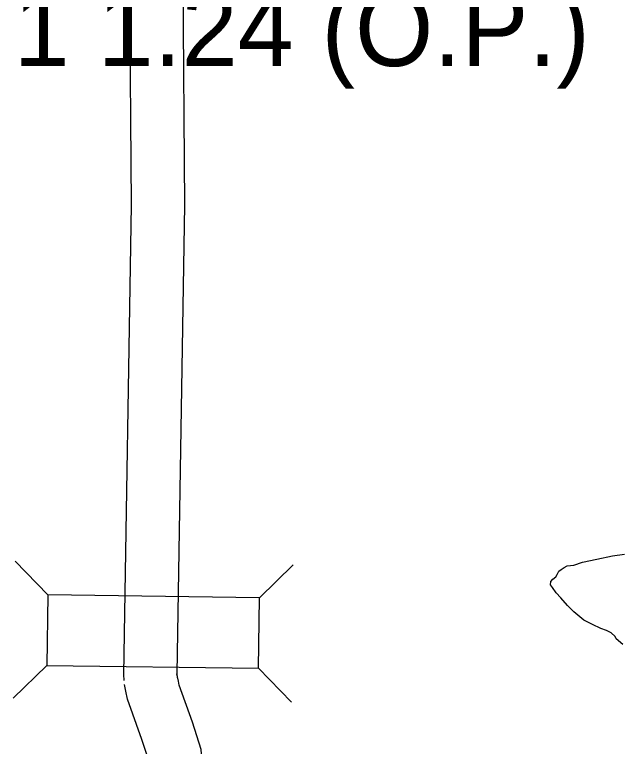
# Model space of a CAD drawing. Extents: x -939622 to -934245, y 1383184 to 1385301.
# Drawn here: x -936403.59 to -936393.44, y 1384587.4 to 1384599.72 of the extents above; entities that cross this region are included whole.
import ezdxf

# ---------------------------------------------------------------- set-up
doc = ezdxf.new("R2010")
doc.units = 0
for name, color, linetype in [('Level 10', 7, 'Continuous'), ('Level 20', 7, 'Continuous'), ('Level 25', 7, 'Continuous'), ('Level 9', 7, 'Continuous')]:
    doc.layers.add(name, color=color, linetype=linetype)

msp = doc.modelspace()

# ---------------------------------------------------------------- linework, layer by layer
at = {"layer": 'Level 10'}
for points in [[(-936400.851, 1384588.552), (-936400.855, 1384588.625), (-936400.726, 1384596.507), (-936400.757, 1384600.262)], [(-936401.75, 1384588.506), (-936401.756, 1384588.609), (-936401.626, 1384596.511), (-936401.656, 1384600.127)], [(-936397.363, 1384579.247), (-936400.098, 1384583.042), (-936400.103, 1384583.052), (-936400.111, 1384583.136), (-936400.436, 1384587.126), (-936400.45, 1384587.342), (-936400.526, 1384587.573), (-936400.601, 1384587.803), (-936400.823, 1384588.429), (-936400.835, 1384588.496), (-936400.86, 1384588.617)], [(-936398.093, 1384578.72), (-936400.861, 1384582.561), (-936400.934, 1384582.695), (-936400.989, 1384582.852), (-936401.008, 1384583.061), (-936401.334, 1384587.062), (-936401.341, 1384587.171), (-936401.381, 1384587.293), (-936401.453, 1384587.513), (-936401.694, 1384588.194), (-936401.719, 1384588.325), (-936401.742, 1384588.441)]]:
    msp.add_lwpolyline(points, dxfattribs=at)
at = {"layer": 'Level 20'}
for p, q in [((-936403.033, 1384589.949), (-936403.586, 1384590.517)), ((-936399.47, 1384589.9), (-936398.902, 1384590.452)), ((-936403.05, 1384588.761), (-936403.618, 1384588.209)), ((-936399.486, 1384588.712), (-936398.934, 1384588.144))]:
    msp.add_line(p, q, dxfattribs=at)
msp.add_lwpolyline([(-936403.05, 1384588.761), (-936399.486, 1384588.712), (-936399.47, 1384589.9), (-936403.033, 1384589.949)], close=True, dxfattribs=at)
at = {"layer": 'Level 9'}
msp.add_lwpolyline([(-936393.352, 1384589.111), (-936393.464, 1384589.206), (-936393.479, 1384589.248), (-936393.548, 1384589.311), (-936393.626, 1384589.35), (-936393.722, 1384589.379), (-936393.866, 1384589.45), (-936394.011, 1384589.521), (-936394.176, 1384589.664), (-936394.285, 1384589.769), (-936394.396, 1384589.897), (-936394.474, 1384589.984), (-936394.535, 1384590.073), (-936394.571, 1384590.118), (-936394.566, 1384590.172), (-936394.53, 1384590.212), (-936394.482, 1384590.251), (-936394.459, 1384590.293), (-936394.432, 1384590.344), (-936394.393, 1384590.375), (-936394.34, 1384590.408), (-936394.289, 1384590.439), (-936394.178, 1384590.445), (-936394.029, 1384590.5), (-936393.79, 1384590.547), (-936393.527, 1384590.606), (-936393.327, 1384590.634)], dxfattribs=at)

# ---------------------------------------------------------------- texts
at = {"layer": 'Level 25'}
msp.add_text('1 1.24 (O.P.)', height=1.2672, dxfattribs=at).set_placement((-936403.608, 1384598.85))

doc.saveas('drawing.dxf')
